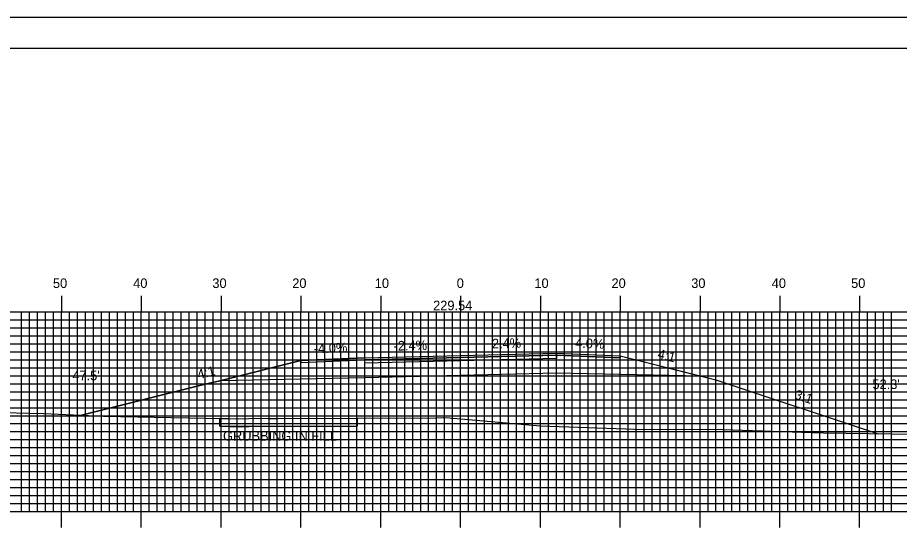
# Model space of a CAD drawing. Extents: x 1803897 to 1804240, y 442591 to 442811.
# Drawn here: x 1804007.2 to 1804117.6, y 442746.2 to 442810.5 of the extents above; entities that cross this region are included whole.
import ezdxf

# ---------------------------------------------------------------- set-up
doc = ezdxf.new("R2010")
doc.units = 0
for name, color, linetype in [('ANNOTATION', 7, 'Continuous'), ('BORDER', 7, 'Continuous'), ('D_Roadway_Centerline', 7, 'Continuous'), ('D_Roadway_Centerline_Text', 7, 'Continuous'), ('D_Roadway_Edge_Shoulder', 7, 'Continuous'), ('D_Roadway_Edge_TW', 7, 'Continuous'), ('D_Roadway_Pavement', 7, 'Continuous'), ('D_Roadway_SlopeLines', 7, 'Continuous'), ('D_Roadway_SubGrade', 7, 'Continuous'), ('D_Text_Standard', 7, 'Continuous'), ('GRUBBING IN FILL', 7, 'Continuous'), ('H_V ANNOTATION', 7, 'Continuous'), ('MAJOR', 7, 'Continuous'), ('MINOR', 7, 'Continuous'), ('PLOT BOUNDARY', 7, 'Continuous'), ('S_Roadway_Centerline', 7, 'Continuous')]:
    doc.layers.add(name, color=color, linetype=linetype)

msp = doc.modelspace()

# ---------------------------------------------------------------- linework, layer by layer
at = {"layer": 'BORDER'}
msp.add_lwpolyline([(1803913.05, 442596.67), (1804233.05, 442596.67), (1804233.05, 442806.67), (1803913.05, 442806.67)], close=True, dxfattribs=at)
at = {"layer": 'D_Roadway_Centerline'}
msp.add_lwpolyline([(1804015.17, 442760.73), (1804030.65, 442764.6), (1804032.48, 442765.05), (1804042.65, 442767.6), (1804050.65, 442767.92), (1804062.65, 442768.21), (1804074.65, 442768.49), (1804082.65, 442768.17), (1804092.83, 442765.63), (1804094.65, 442765.17), (1804114.95, 442758.41)], dxfattribs=at)
at = {"layer": 'D_Roadway_Edge_Shoulder'}
for points in [[(1804050.65, 442767.92), (1804042.65, 442767.6), (1804042.65, 442767.35), (1804050.65, 442767.67)], [(1804074.65, 442768.49), (1804082.65, 442768.17), (1804082.65, 442767.92), (1804074.65, 442768.24)]]:
    msp.add_lwpolyline(points, close=True, dxfattribs=at)
at = {"layer": 'D_Roadway_Edge_TW'}
msp.add_lwpolyline([(1804050.65, 442767.67), (1804050.65, 442767.92), (1804062.65, 442768.21), (1804074.65, 442768.49), (1804074.65, 442768.24), (1804062.65, 442767.96)], close=True, dxfattribs=at)
at = {"layer": 'D_Roadway_Pavement'}
msp.add_lwpolyline([(1804050.65, 442767.25), (1804050.65, 442767.67), (1804062.65, 442767.96), (1804074.65, 442768.24), (1804074.65, 442767.83), (1804062.65, 442767.54)], close=True, dxfattribs=at)
at = {"layer": 'D_Roadway_SlopeLines'}
for points in [[(1804042.65, 442767.6), (1804032.48, 442765.05), (1804030.65, 442764.6), (1804015.17, 442760.73)], [(1804082.65, 442768.17), (1804094.65, 442765.17), (1804114.95, 442758.41)]]:
    msp.add_lwpolyline(points, dxfattribs=at)
at = {"layer": 'D_Roadway_SubGrade'}
msp.add_lwpolyline([(1804050.65, 442765.42), (1804032.48, 442765.05), (1804042.65, 442767.6), (1804042.65, 442767.35), (1804050.65, 442767.67), (1804062.65, 442767.96), (1804074.65, 442768.24), (1804082.65, 442767.92), (1804082.65, 442768.17), (1804092.83, 442765.63), (1804074.65, 442765.99), (1804062.65, 442765.71)], close=True, dxfattribs=at)
at = {"layer": 'GRUBBING IN FILL'}
for p, q in [((1804032.48, 442760.34), (1804032.48, 442759.34)), ((1804032.48, 442760.34), (1804032.48, 442759.34)), ((1804049.69, 442759.35), (1804049.69, 442760.35)), ((1804049.69, 442759.35), (1804049.69, 442760.35))]:
    msp.add_line(p, q, dxfattribs=at)
msp.add_lwpolyline([(1804032.48, 442760.34), (1804034.88, 442760.29), (1804037.39, 442760.34), (1804038.54, 442760.32), (1804039.69, 442760.3), (1804049.69, 442760.35), (1804049.69, 442759.35), (1804044.69, 442759.33), (1804039.69, 442759.3), (1804036.13, 442759.32), (1804033.68, 442759.32), (1804032.48, 442759.34)], close=True, dxfattribs=at)
msp.add_lwpolyline([(1804032.48, 442760.34), (1804034.88, 442760.29), (1804037.39, 442760.34), (1804038.54, 442760.32), (1804039.69, 442760.3), (1804049.69, 442760.35), (1804049.69, 442759.35), (1804044.69, 442759.33), (1804039.69, 442759.3), (1804036.13, 442759.32), (1804033.68, 442759.32), (1804032.48, 442759.34)], close=True, dxfattribs=at)
msp.add_lwpolyline([(1804032.48, 442759.34), (1804034.88, 442759.29), (1804037.39, 442759.34), (1804039.69, 442759.3), (1804049.69, 442759.35)], dxfattribs=at)
msp.add_lwpolyline([(1804032.48, 442759.34), (1804034.88, 442759.29), (1804037.39, 442759.34), (1804039.69, 442759.3), (1804049.69, 442759.35)], dxfattribs=at)
at = {"layer": 'MAJOR'}
for p, q in [((1804012.65, 442775.67), (1804012.65, 442773.67)), ((1804022.65, 442775.67), (1804022.65, 442773.67)), ((1804032.65, 442775.67), (1804032.65, 442773.67)), ((1804042.65, 442775.67), (1804042.65, 442773.67)), ((1804052.65, 442775.67), (1804052.65, 442773.67)), ((1804062.65, 442775.67), (1804062.65, 442773.67)), ((1804072.65, 442775.67), (1804072.65, 442773.67)), ((1804082.65, 442775.67), (1804082.65, 442773.67)), ((1804092.65, 442775.67), (1804092.65, 442773.67)), ((1804102.65, 442775.67), (1804102.65, 442773.67)), ((1804112.65, 442775.67), (1804112.65, 442773.67)), ((1803922.65, 442773.67), (1804202.65, 442773.67)), ((1803922.65, 442773.67), (1804202.65, 442773.67)), ((1804012.65, 442748.67), (1804012.65, 442773.67)), ((1804022.65, 442748.67), (1804022.65, 442773.67)), ((1804032.65, 442748.67), (1804032.65, 442773.67)), ((1804042.65, 442748.67), (1804042.65, 442773.67)), ((1804052.65, 442748.67), (1804052.65, 442773.67)), ((1804062.65, 442748.67), (1804062.65, 442773.67)), ((1804072.65, 442748.67), (1804072.65, 442773.67)), ((1804082.65, 442748.67), (1804082.65, 442773.67)), ((1804092.65, 442748.67), (1804092.65, 442773.67)), ((1804102.65, 442748.67), (1804102.65, 442773.67)), ((1804112.65, 442748.67), (1804112.65, 442773.67)), ((1803922.65, 442768.67), (1804202.65, 442768.67)), ((1803922.65, 442763.67), (1804202.65, 442763.67)), ((1803922.65, 442758.67), (1804202.65, 442758.67)), ((1803922.65, 442753.67), (1804202.65, 442753.67)), ((1803922.65, 442748.67), (1804202.65, 442748.67)), ((1803922.65, 442748.67), (1804202.65, 442748.67)), ((1804012.65, 442746.66), (1804012.65, 442748.67)), ((1804022.65, 442746.66), (1804022.65, 442748.67)), ((1804032.65, 442746.66), (1804032.65, 442748.67)), ((1804042.65, 442746.66), (1804042.65, 442748.67)), ((1804052.65, 442746.66), (1804052.65, 442748.67)), ((1804062.65, 442746.66), (1804062.65, 442748.67)), ((1804072.65, 442746.66), (1804072.65, 442748.67)), ((1804082.65, 442746.66), (1804082.65, 442748.67)), ((1804092.65, 442746.66), (1804092.65, 442748.67)), ((1804102.65, 442746.66), (1804102.65, 442748.67)), ((1804112.65, 442746.66), (1804112.65, 442748.67))]:
    msp.add_line(p, q, dxfattribs=at)
at = {"layer": 'MINOR'}
for p, q in [((1804007.65, 442748.67), (1804007.65, 442773.67)), ((1804008.65, 442748.67), (1804008.65, 442773.67)), ((1804009.65, 442748.67), (1804009.65, 442773.67)), ((1804010.65, 442748.67), (1804010.65, 442773.67)), ((1804011.65, 442748.67), (1804011.65, 442773.67)), ((1804013.65, 442748.67), (1804013.65, 442773.67)), ((1804014.65, 442748.67), (1804014.65, 442773.67)), ((1804015.65, 442748.67), (1804015.65, 442773.67)), ((1804016.65, 442748.67), (1804016.65, 442773.67)), ((1804017.65, 442748.67), (1804017.65, 442773.67)), ((1804018.65, 442748.67), (1804018.65, 442773.67)), ((1804019.65, 442748.67), (1804019.65, 442773.67)), ((1804020.65, 442748.67), (1804020.65, 442773.67)), ((1804021.65, 442748.67), (1804021.65, 442773.67)), ((1804023.65, 442748.67), (1804023.65, 442773.67)), ((1804024.65, 442748.67), (1804024.65, 442773.67)), ((1804025.65, 442748.67), (1804025.65, 442773.67)), ((1804026.65, 442748.67), (1804026.65, 442773.67)), ((1804027.65, 442748.67), (1804027.65, 442773.67)), ((1804028.65, 442748.67), (1804028.65, 442773.67)), ((1804029.65, 442748.67), (1804029.65, 442773.67)), ((1804030.65, 442748.67), (1804030.65, 442773.67)), ((1804031.65, 442748.67), (1804031.65, 442773.67)), ((1804033.65, 442748.67), (1804033.65, 442773.67)), ((1804034.65, 442748.67), (1804034.65, 442773.67)), ((1804035.65, 442748.67), (1804035.65, 442773.67)), ((1804036.65, 442748.67), (1804036.65, 442773.67)), ((1804037.65, 442748.67), (1804037.65, 442773.67)), ((1804038.65, 442748.67), (1804038.65, 442773.67)), ((1804039.65, 442748.67), (1804039.65, 442773.67)), ((1804040.65, 442748.67), (1804040.65, 442773.67)), ((1804041.65, 442748.67), (1804041.65, 442773.67)), ((1804043.65, 442748.67), (1804043.65, 442773.67)), ((1804044.65, 442748.67), (1804044.65, 442773.67)), ((1804045.65, 442748.67), (1804045.65, 442773.67)), ((1804046.65, 442748.67), (1804046.65, 442773.67)), ((1804047.65, 442748.67), (1804047.65, 442773.67)), ((1804048.65, 442748.67), (1804048.65, 442773.67)), ((1804049.65, 442748.67), (1804049.65, 442773.67)), ((1804050.65, 442748.67), (1804050.65, 442773.67)), ((1804051.65, 442748.67), (1804051.65, 442773.67)), ((1804053.65, 442748.67), (1804053.65, 442773.67)), ((1804054.65, 442748.67), (1804054.65, 442773.67)), ((1804055.65, 442748.67), (1804055.65, 442773.67)), ((1804056.65, 442748.67), (1804056.65, 442773.67)), ((1804057.65, 442748.67), (1804057.65, 442773.67)), ((1804058.65, 442748.67), (1804058.65, 442773.67)), ((1804059.65, 442748.67), (1804059.65, 442773.67)), ((1804060.65, 442748.67), (1804060.65, 442773.67)), ((1804061.65, 442748.67), (1804061.65, 442773.67)), ((1804063.65, 442748.67), (1804063.65, 442773.67)), ((1804064.65, 442748.67), (1804064.65, 442773.67)), ((1804065.65, 442748.67), (1804065.65, 442773.67)), ((1804066.65, 442748.67), (1804066.65, 442773.67)), ((1804067.65, 442748.67), (1804067.65, 442773.67)), ((1804068.65, 442748.67), (1804068.65, 442773.67)), ((1804069.65, 442748.67), (1804069.65, 442773.67)), ((1804070.65, 442748.67), (1804070.65, 442773.67)), ((1804071.65, 442748.67), (1804071.65, 442773.67)), ((1804073.65, 442748.67), (1804073.65, 442773.67)), ((1804074.65, 442748.67), (1804074.65, 442773.67)), ((1804075.65, 442748.67), (1804075.65, 442773.67)), ((1804076.65, 442748.67), (1804076.65, 442773.67)), ((1804077.65, 442748.67), (1804077.65, 442773.67)), ((1804078.65, 442748.67), (1804078.65, 442773.67)), ((1804079.65, 442748.67), (1804079.65, 442773.67)), ((1804080.65, 442748.67), (1804080.65, 442773.67)), ((1804081.65, 442748.67), (1804081.65, 442773.67)), ((1804083.65, 442748.67), (1804083.65, 442773.67)), ((1804084.65, 442748.67), (1804084.65, 442773.67)), ((1804085.65, 442748.67), (1804085.65, 442773.67)), ((1804086.65, 442748.67), (1804086.65, 442773.67)), ((1804087.65, 442748.67), (1804087.65, 442773.67)), ((1804088.65, 442748.67), (1804088.65, 442773.67)), ((1804089.65, 442748.67), (1804089.65, 442773.67)), ((1804090.65, 442748.67), (1804090.65, 442773.67)), ((1804091.65, 442748.67), (1804091.65, 442773.67)), ((1804093.65, 442748.67), (1804093.65, 442773.67)), ((1804094.65, 442748.67), (1804094.65, 442773.67)), ((1804095.65, 442748.67), (1804095.65, 442773.67)), ((1804096.65, 442748.67), (1804096.65, 442773.67)), ((1804097.65, 442748.67), (1804097.65, 442773.67)), ((1804098.65, 442748.67), (1804098.65, 442773.67)), ((1804099.65, 442748.67), (1804099.65, 442773.67)), ((1804100.65, 442748.67), (1804100.65, 442773.67)), ((1804101.65, 442748.67), (1804101.65, 442773.67)), ((1804103.65, 442748.67), (1804103.65, 442773.67)), ((1804104.65, 442748.67), (1804104.65, 442773.67)), ((1804105.65, 442748.67), (1804105.65, 442773.67)), ((1804106.65, 442748.67), (1804106.65, 442773.67)), ((1804107.65, 442748.67), (1804107.65, 442773.67)), ((1804108.65, 442748.67), (1804108.65, 442773.67)), ((1804109.65, 442748.67), (1804109.65, 442773.67)), ((1804110.65, 442748.67), (1804110.65, 442773.67)), ((1804111.65, 442748.67), (1804111.65, 442773.67)), ((1804113.65, 442748.67), (1804113.65, 442773.67)), ((1804114.65, 442748.67), (1804114.65, 442773.67)), ((1804115.65, 442748.67), (1804115.65, 442773.67)), ((1804116.65, 442748.67), (1804116.65, 442773.67)), ((1803922.65, 442772.67), (1804202.65, 442772.67)), ((1803922.65, 442771.67), (1804202.65, 442771.67)), ((1803922.65, 442770.67), (1804202.65, 442770.67)), ((1803922.65, 442769.67), (1804202.65, 442769.67)), ((1803922.65, 442767.67), (1804202.65, 442767.67)), ((1803922.65, 442766.67), (1804202.65, 442766.67)), ((1803922.65, 442765.67), (1804202.65, 442765.67)), ((1803922.65, 442764.67), (1804202.65, 442764.67)), ((1803922.65, 442762.67), (1804202.65, 442762.67)), ((1803922.65, 442761.67), (1804202.65, 442761.67)), ((1803922.65, 442760.67), (1804202.65, 442760.67)), ((1803922.65, 442759.67), (1804202.65, 442759.67)), ((1803922.65, 442757.67), (1804202.65, 442757.67)), ((1803922.65, 442756.67), (1804202.65, 442756.67)), ((1803922.65, 442755.67), (1804202.65, 442755.67)), ((1803922.65, 442754.67), (1804202.65, 442754.67)), ((1803922.65, 442752.67), (1804202.65, 442752.67)), ((1803922.65, 442751.67), (1804202.65, 442751.67)), ((1803922.65, 442750.67), (1804202.65, 442750.67)), ((1803922.65, 442749.67), (1804202.65, 442749.67))]:
    msp.add_line(p, q, dxfattribs=at)
at = {"layer": 'PLOT BOUNDARY'}
msp.add_lwpolyline([(1803896.87, 442590.55), (1804236.87, 442590.55), (1804236.87, 442810.55), (1803896.87, 442810.55)], close=True, dxfattribs=at)
at = {"layer": 'S_Roadway_Centerline'}
msp.add_lwpolyline([(1804003.55, 442761.09), (1804010.38, 442760.96), (1804017.91, 442760.59), (1804034.88, 442760.29), (1804037.39, 442760.34), (1804039.69, 442760.3), (1804059.69, 442760.41), (1804060.51, 442760.42), (1804061.27, 442760.38), (1804072.64, 442759.39), (1804083.37, 442759), (1804084.46, 442758.97), (1804095.49, 442758.92), (1804106.65, 442758.55), (1804108.12, 442758.51), (1804119.42, 442758.34)], dxfattribs=at)

# ---------------------------------------------------------------- texts
at = {"layer": 'ANNOTATION'}
for s, rotation, p in [('-4.0%', 2.2906, (1804044.29, 442768.47)), ('-2.4%', 1.3748, (1804054.27, 442768.81)), ('2.4%', 1.3748, (1804066.59, 442769.1)), ('-4.0%', 357.7094, (1804076.45, 442769.22)), ('4:1', 345.9638, (1804087.25, 442767.89)), ('4:1', 14.0362, (1804029.83, 442765.22)), ('3:1', 341.5652, (1804104.4, 442762.83))]:
    msp.add_text(s, height=1.2, rotation=rotation, dxfattribs=at).set_placement(p)
at = {"layer": 'D_Roadway_Centerline'}
for s, p in [('C', (1804062.65, 442768.21)), ('L', (1804062.65, 442768.2))]:
    msp.add_text(s, height=0.0146, dxfattribs=at).set_placement(p)
at = {"layer": 'D_Roadway_Centerline_Text'}
msp.add_text('229.54', height=1.2, dxfattribs=at).set_placement((1804059.21, 442773.88))
at = {"layer": 'D_Text_Standard'}
for s, p in [("47.5'", (1804014.01, 442765.1)), ("52.3'", (1804114.25, 442764.01))]:
    msp.add_text(s, height=1.2, dxfattribs=at).set_placement(p)
at = {"layer": 'GRUBBING IN FILL'}
msp.add_text('GRUBBING IN FILL', height=1.2, rotation=359.9775, dxfattribs=at).set_placement((1804032.89, 442757.54))
at = {"layer": 'H_V ANNOTATION'}
for s, p in [('50', (1804011.58, 442776.67)), ('40', (1804021.63, 442776.67)), ('30', (1804031.55, 442776.67)), ('20', (1804041.56, 442776.67)), ('10', (1804051.9, 442776.67)), ('0', (1804062.17, 442776.67)), ('10', (1804071.9, 442776.67)), ('20', (1804081.56, 442776.67)), ('30', (1804091.55, 442776.67)), ('40', (1804101.63, 442776.67)), ('50', (1804111.58, 442776.67))]:
    msp.add_text(s, height=1.2, dxfattribs=at).set_placement(p)

doc.saveas('drawing.dxf')
